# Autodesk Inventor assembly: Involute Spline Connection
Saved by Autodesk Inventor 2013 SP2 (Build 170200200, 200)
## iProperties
Created: 2020-02
Part Number: Involute Spline Connection
Document SubType Name: Assembly
Designer: DELL
ClientObjectVersion: 1
Author: DELL
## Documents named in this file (1)
- C:\Users\DELL\Dropbox\Inventor\Projects\Quadcopter F450\Assemblies\Servo - Design Accelerator Spline Tutorial\Servo Accelerator Spline Makeup\Design Accelerator\Involute Spline Connection1.iam
